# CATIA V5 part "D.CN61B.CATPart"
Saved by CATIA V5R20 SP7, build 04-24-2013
Part number: D.CN61B
Material "Nessuno"
Bounding box of the stored display mesh (mm): x 0 to 150.807, y -131.181 to 0, z -91.151 to 75.737
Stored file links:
  C:\Users\designer2\Desktop\Ottobre 2022\25-10-2022\04\Yori Evo 48V\D.CN61B.CATPart
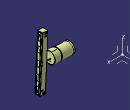
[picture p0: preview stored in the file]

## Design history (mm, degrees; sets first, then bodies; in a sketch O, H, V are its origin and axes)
AxisSystem1: origin (0, 0, 0), X (1, 0, 0), Y (0, 1, 0), Z (0, 0, 1)
Set1
  DatumSurface1
Body1 (main body), material "Nessuno"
